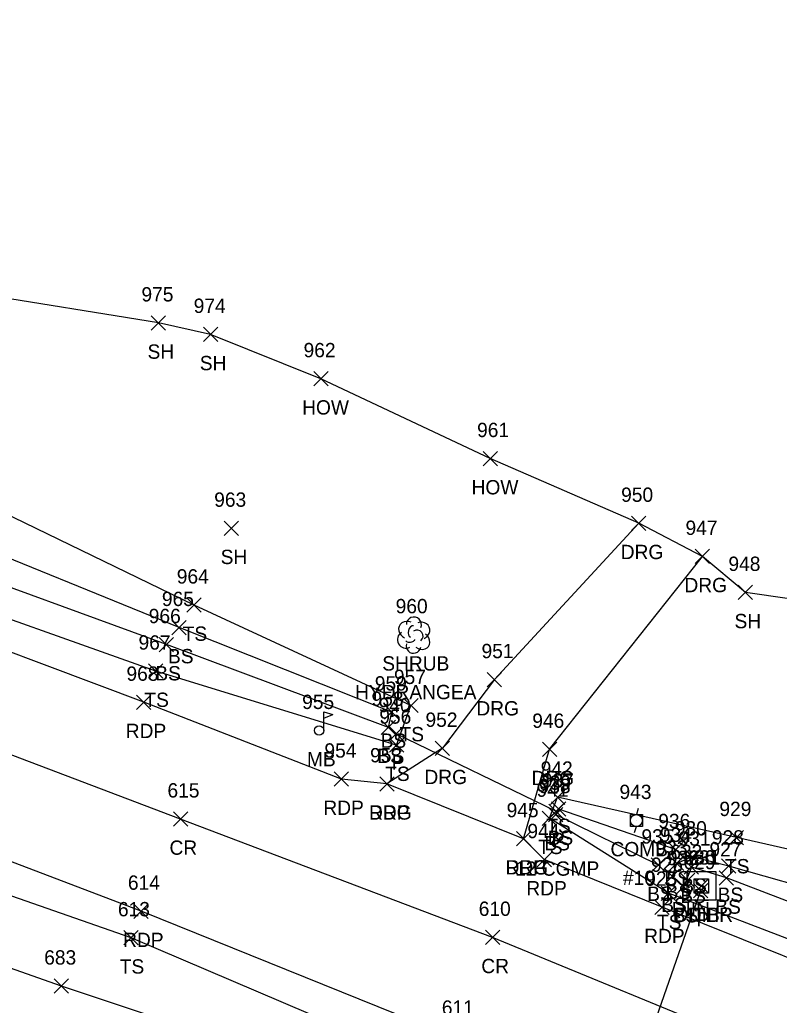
# Model space of a CAD drawing. Extents: x 1599569 to 1610055, y 642560 to 647860.
# Drawn here: x 1602781.6 to 1602887.6, y 647435 to 647572.7 of the extents above; entities that cross this region are included whole.
import ezdxf

# ---------------------------------------------------------------- set-up
doc = ezdxf.new("R2010")
doc.units = 0
for name, color, linetype in [('D_A', 7, 'Continuous'), ('D_C', 7, 'Continuous'), ('D_I', 7, 'Continuous'), ('D_TIC', 7, 'Continuous'), ('DCP', 7, 'Continuous'), ('DS', 7, 'Continuous'), ('L_A', 7, 'Continuous'), ('L_C', 7, 'Continuous'), ('L_I', 7, 'Continuous'), ('L_TIC', 7, 'Continuous'), ('LBC', 7, 'Continuous'), ('LELB', 7, 'Continuous'), ('LMB', 7, 'Continuous'), ('LSH', 7, 'Continuous'), ('LSOGP', 7, 'Continuous'), ('P_A', 7, 'Continuous'), ('P_I', 7, 'Continuous'), ('P_TIC', 7, 'Continuous'), ('PET', 7, 'Continuous'), ('PRC', 7, 'Continuous'), ('R_A', 7, 'Continuous'), ('R_I', 7, 'Continuous'), ('R_TIC', 7, 'Continuous'), ('RDG', 7, 'Continuous'), ('U_A', 7, 'Continuous'), ('U_C', 7, 'Continuous'), ('U_I', 7, 'Continuous'), ('UP', 7, 'Continuous')]:
    doc.layers.add(name, color=color, linetype=linetype)

msp = doc.modelspace()

# ---------------------------------------------------------------- linework, layer by layer
at = {"layer": 'D_TIC'}
for points in [[(1602833.13, 647471.97), (1602835.13, 647473.97)], [(1602835.13, 647471.97), (1602833.13, 647473.97)], [(1602855.42, 647461.14), (1602857.42, 647463.14)], [(1602857.42, 647461.14), (1602855.42, 647463.14)], [(1602873.78, 647451.48), (1602875.78, 647453.48)], [(1602875.78, 647451.48), (1602873.78, 647453.48)], [(1602875.7, 647450.69), (1602877.7, 647452.69)], [(1602877.7, 647450.69), (1602875.7, 647452.69)], [(1602875.62, 647450.06), (1602877.62, 647452.06)], [(1602877.62, 647450.06), (1602875.62, 647452.06)]]:
    msp.add_lwpolyline(points, dxfattribs=at)
at = {"layer": 'DCP'}
for points in [[(1602856.42, 647462.14), (1602834.13, 647472.97)], [(1602857.51, 647396.27), (1602876.62, 647451.06)]]:
    msp.add_lwpolyline(points, dxfattribs=at)
at = {"layer": 'DS'}
for p, q in [((1602874.71, 647453.71), (1602878.71, 647453.71)), ((1602874.71, 647449.71), (1602874.72, 647453.71)), ((1602875.71, 647452.71), (1602877.71, 647452.71)), ((1602875.71, 647450.71), (1602875.71, 647452.71)), ((1602877.71, 647452.71), (1602877.71, 647450.71)), ((1602878.71, 647453.71), (1602878.71, 647449.71)), ((1602876.71, 647451.72), (1602876.71, 647451.72)), ((1602877.71, 647450.71), (1602875.71, 647450.71)), ((1602878.71, 647449.71), (1602874.71, 647449.71)), ((1602877.21, 647449.71), (1602877.71, 647449.71))]:
    msp.add_line(p, q, dxfattribs=at)
at = {"layer": 'L_TIC'}
for points in [[(1602799.94, 647529.33), (1602801.94, 647531.33)], [(1602801.94, 647529.33), (1602799.94, 647531.33)], [(1602807.23, 647527.73), (1602809.23, 647529.73)], [(1602809.23, 647527.73), (1602807.23, 647529.73)], [(1602822.61, 647521.54), (1602824.61, 647523.54)], [(1602824.61, 647521.54), (1602822.61, 647523.54)], [(1602846.25, 647510.39), (1602848.25, 647512.39)], [(1602848.25, 647510.39), (1602846.25, 647512.39)], [(1602810.14, 647500.66), (1602812.14, 647502.66)], [(1602812.14, 647500.66), (1602810.14, 647502.66)], [(1602881.84, 647491.7), (1602883.84, 647493.7)], [(1602883.84, 647491.7), (1602881.84, 647493.7)], [(1602804.92, 647489.94), (1602806.92, 647491.94)], [(1602806.92, 647489.94), (1602804.92, 647491.94)], [(1602802.84, 647486.8), (1602804.84, 647488.8)], [(1602804.84, 647486.8), (1602802.84, 647488.8)], [(1602801.07, 647484.41), (1602803.07, 647486.41)], [(1602803.07, 647484.41), (1602801.07, 647486.41)], [(1602799.58, 647480.71), (1602801.58, 647482.71)], [(1602801.58, 647480.71), (1602799.58, 647482.71)], [(1602835.18, 647475.91), (1602837.18, 647477.91)], [(1602837.18, 647475.91), (1602835.18, 647477.91)], [(1602832.51, 647475), (1602834.51, 647477)], [(1602834.51, 647475), (1602832.51, 647477)], [(1602832.04, 647472.86), (1602834.04, 647474.86)], [(1602834.04, 647472.86), (1602832.04, 647474.86)], [(1602832.04, 647472.86), (1602834.04, 647474.86)], [(1602834.04, 647472.86), (1602832.04, 647474.86)], [(1602833.18, 647470.37), (1602835.18, 647472.37)], [(1602835.18, 647470.37), (1602833.18, 647472.37)], [(1602833.18, 647470.37), (1602835.18, 647472.37)], [(1602835.18, 647470.37), (1602833.18, 647472.37)], [(1602855.65, 647463.1), (1602857.65, 647465.1)], [(1602857.65, 647463.1), (1602855.65, 647465.1)], [(1602855.65, 647463.1), (1602857.65, 647465.1)], [(1602857.65, 647463.1), (1602855.65, 647465.1)], [(1602855.36, 647460.68), (1602857.36, 647462.68)], [(1602857.36, 647460.68), (1602855.36, 647462.68)], [(1602855.36, 647460.68), (1602857.36, 647462.68)], [(1602857.36, 647460.68), (1602855.36, 647462.68)], [(1602855.81, 647461.45), (1602857.81, 647463.45)], [(1602857.81, 647461.45), (1602855.81, 647463.45)], [(1602854.51, 647460.16), (1602856.51, 647462.16)], [(1602856.51, 647460.16), (1602854.51, 647462.16)], [(1602880.59, 647457.47), (1602882.59, 647459.47)], [(1602882.59, 647457.47), (1602880.59, 647459.47)], [(1602872.11, 647455.78), (1602874.11, 647457.78)], [(1602874.11, 647455.78), (1602872.11, 647457.78)], [(1602869.7, 647453.63), (1602871.7, 647455.63)], [(1602871.7, 647453.63), (1602869.7, 647455.63)], [(1602869.7, 647453.63), (1602871.7, 647455.63)], [(1602871.7, 647453.63), (1602869.7, 647455.63)], [(1602872.27, 647453.86), (1602874.27, 647455.86)], [(1602874.27, 647453.86), (1602872.27, 647455.86)], [(1602872.27, 647453.86), (1602874.27, 647455.86)], [(1602874.27, 647453.86), (1602872.27, 647455.86)], [(1602874.44, 647454.76), (1602876.44, 647456.76)], [(1602876.44, 647454.76), (1602874.44, 647456.76)], [(1602879.53, 647453.49), (1602881.53, 647455.49)], [(1602881.53, 647453.49), (1602879.53, 647455.49)], [(1602871.66, 647452.06), (1602873.66, 647454.06)], [(1602873.66, 647452.06), (1602871.66, 647454.06)], [(1602874.32, 647453.34), (1602876.32, 647455.34)], [(1602876.32, 647453.34), (1602874.32, 647455.34)], [(1602879.19, 647451.83), (1602881.19, 647453.83)], [(1602881.19, 647451.83), (1602879.19, 647453.83)], [(1602871.1, 647449.68), (1602873.1, 647451.68)], [(1602873.1, 647449.68), (1602871.1, 647451.68)], [(1602873.25, 647450.62), (1602875.25, 647452.62)], [(1602875.25, 647450.62), (1602873.25, 647452.62)], [(1602796.14, 647443.47), (1602798.14, 647445.47)], [(1602798.14, 647443.47), (1602796.14, 647445.47)], [(1602786.42, 647436.73), (1602788.42, 647438.73)], [(1602788.42, 647436.73), (1602786.42, 647438.73)]]:
    msp.add_lwpolyline(points, dxfattribs=at)
at = {"layer": 'LBC'}
msp.add_lwpolyline([(1602847.25, 647511.39), (1602823.61, 647522.54)], dxfattribs=at)
at = {"layer": 'LELB'}
for points in [[(1602833.04, 647473.86), (1602802.07, 647485.41), (1602768.67, 647497.63), (1602737.77, 647507.38), (1602714.1, 647514.6), (1602693.54, 647524.87), (1602693.84, 647532.12)], [(1602834.18, 647471.37), (1602800.58, 647481.71), (1602766.83, 647493.71), (1602735.94, 647503.84), (1602713.49, 647512.26), (1602692.59, 647522.64), (1602679.82, 647526.83)], [(1602834.18, 647471.37), (1602836.18, 647476.91), (1602805.92, 647490.94), (1602772.81, 647507), (1602747.82, 647515.86)], [(1602833.04, 647473.86), (1602833.51, 647476), (1602803.84, 647487.8), (1602770.45, 647501.41), (1602739.01, 647512.67)], [(1602920.15, 647395.93), (1602878.36, 647413), (1602839.66, 647426.29), (1602797.14, 647444.47), (1602757.03, 647458.46), (1602729.83, 647462.67), (1602705.16, 647473.23), (1602676.17, 647483.37), (1602645.06, 647491.74), (1602608.39, 647499.39), (1602581.9, 647503.71), (1602538.18, 647509.07), (1602515.71, 647510.39), (1602496.95, 647511.81), (1602468.81, 647510.52), (1602437.53, 647504.14), (1602407.66, 647504.45), (1602378.45, 647504.43), (1602350.14, 647499.82), (1602309.52, 647489.18), (1602272.83, 647479.89), (1602236.83, 647468.86)], [(1602844.82, 647413.51), (1602810.8, 647429.9), (1602787.42, 647437.73), (1602740.96, 647454.08), (1602700.04, 647463.04), (1602670.27, 647463.75), (1602639.01, 647474.07), (1602621.95, 647482.89), (1602620.57, 647490.49), (1602611.15, 647487.69), (1602600.84, 647483.48), (1602570.08, 647479.67), (1602551.04, 647482.68)], [(1603024.48, 647432.95), (1603024.71, 647411.16), (1603022.25, 647401.19), (1603020.95, 647395.76), (1603017.49, 647392.33), (1602977.99, 647408.75), (1602939, 647424.29), (1602906.12, 647437.67), (1602872.1, 647450.68), (1602855.51, 647461.16), (1602856.65, 647464.1)], [(1603020.03, 647406.1), (1602986.07, 647424.37), (1602946.6, 647442.8), (1602913.72, 647451.19), (1602881.59, 647458.47), (1602856.65, 647464.1)], [(1602870.7, 647454.63), (1602873.11, 647456.78), (1602856.81, 647462.45), (1602856.36, 647461.68)], [(1602870.7, 647454.63), (1602856.36, 647461.68)], [(1603018.88, 647397.59), (1603018.7, 647403.49), (1602982.82, 647417.97), (1602942.23, 647433.49), (1602910.75, 647445.93), (1602880.53, 647454.49), (1602875.44, 647455.76), (1602873.27, 647454.86)], [(1603018.88, 647397.59), (1602980.19, 647413.24), (1602940.49, 647427.7), (1602908.49, 647441.99), (1602880.19, 647452.83), (1602875.32, 647454.34), (1602874.25, 647451.62), (1602872.66, 647453.06), (1602873.27, 647454.86)]]:
    msp.add_lwpolyline(points, dxfattribs=at)
at = {"layer": 'LMB'}
for p, q in [((1602824.01, 647476.02), (1602825.3, 647475.64)), ((1602824.02, 647473.43), (1602824.01, 647476.02)), ((1602824.01, 647475.12), (1602825.3, 647475.63)), ((1602823.36, 647473.42), (1602823.36, 647473.42))]:
    msp.add_line(p, q, dxfattribs=at)
msp.add_circle((1602823.36, 647473.42), 0.656, dxfattribs=at)
at = {"layer": 'LSH'}
msp.add_line((1602836.55, 647486.79), (1602836.55, 647486.79), dxfattribs=at)
msp.add_line((1602836.55, 647486.79), (1602836.55, 647486.79), dxfattribs=at)
msp.add_arc((1602836.59, 647488.22), 1.05, 335.5272, 180.9563, dxfattribs=at)
for centre, major_axis, ratio, start_param, end_param in [((1602835.75, 647487.45), (1.21, -0.51), 0.895232, 1.570796, 4.712389), ((1602837.59, 647487.37), (-1.14, -0.48), 0.949671, 1.570796, 4.712389), ((1602835.46, 647486.08), (0.58, -1.04), 0.959034, 3.141593, 6.283185), ((1602836.34, 647487.25), (-0.208, -0.792), 0.645439, 3.141593, 6.283185), ((1602837.05, 647486.62), (-0.5, 0.667), 0.989748, 3.141593, 6.283185), ((1602836.09, 647486.04), (-0.625, -0.083), 0.423636, 0, 3.141593), ((1602837.55, 647485.95), (-1.09, 0.79), 0.841452, 1.570796, 4.712389), ((1602836.55, 647485.29), (0.26, 1.06), 0.942809, 1.570796, 4.712389)]:
    msp.add_ellipse(centre, major_axis=major_axis, ratio=ratio, start_param=start_param, end_param=end_param, dxfattribs=at)
at = {"layer": 'LSOGP'}
msp.add_lwpolyline([(1602895.48, 647490.88), (1602882.84, 647492.7), (1602876.85, 647497.73), (1602867.96, 647502.35), (1602847.25, 647511.39), (1602823.62, 647522.54), (1602808.23, 647528.73), (1602800.94, 647530.33), (1602775.58, 647534.44), (1602752.66, 647541.91), (1602749.58, 647545.47), (1602732.53, 647552.91), (1602721.69, 647559.94), (1602714.59, 647563.56), (1602695.08, 647572.68), (1602683.13, 647572.17), (1602662.81, 647569.57), (1602657.01, 647571.28), (1602651.21, 647570.55), (1602637.16, 647571.21)], dxfattribs=at)
at = {"layer": 'P_TIC'}
for points in [[(1602797.9, 647476.36), (1602799.9, 647478.36)], [(1602799.9, 647476.36), (1602797.9, 647478.36)], [(1602825.47, 647465.63), (1602827.47, 647467.63)], [(1602827.47, 647465.63), (1602825.47, 647467.63)], [(1602831.84, 647464.97), (1602833.84, 647466.97)], [(1602833.84, 647464.97), (1602831.84, 647466.97)], [(1602803.05, 647460.06), (1602805.05, 647462.06)], [(1602805.05, 647460.06), (1602803.05, 647462.06)], [(1602850.89, 647457.31), (1602852.89, 647459.31)], [(1602852.89, 647457.31), (1602850.89, 647459.31)], [(1602853.79, 647454.39), (1602855.79, 647456.39)], [(1602855.79, 647454.39), (1602853.79, 647456.39)], [(1602797.53, 647447.18), (1602799.53, 647449.18)], [(1602799.53, 647447.18), (1602797.53, 647449.18)], [(1602870.23, 647447.73), (1602872.23, 647449.73)], [(1602872.23, 647447.73), (1602870.23, 647449.73)], [(1602846.57, 647443.53), (1602848.57, 647445.53)], [(1602848.57, 647443.53), (1602846.57, 647445.53)]]:
    msp.add_lwpolyline(points, dxfattribs=at)
at = {"layer": 'PET'}
for points in [[(1602905.04, 647435.16), (1602871.23, 647448.73), (1602854.79, 647455.39), (1602851.89, 647458.31), (1602832.84, 647465.97), (1602826.47, 647466.63), (1602798.9, 647477.36), (1602764.94, 647490.12), (1602734.4, 647501.05), (1602712.01, 647507.82), (1602692.31, 647514.03), (1602689.68, 647516.42), (1602659.67, 647523.94), (1602639.42, 647528.36)], [(1602921.43, 647398.55), (1602879.84, 647415.39), (1602841.76, 647430.73), (1602798.53, 647448.18), (1602759.07, 647463.24), (1602733.65, 647472.41), (1602708.76, 647480.61), (1602673.93, 647491.11), (1602636.13, 647499.95), (1602599.54, 647506.52), (1602572.66, 647510.09), (1602538.1, 647513.57), (1602515.34, 647514.89), (1602496.48, 647515.72), (1602467.73, 647515.18), (1602434.16, 647513.35), (1602407.64, 647511.45), (1602378.14, 647507.95), (1602349.73, 647503.67), (1602307.56, 647494.3), (1602272.4, 647484.22), (1602235.37, 647472.94)]]:
    msp.add_lwpolyline(points, dxfattribs=at)
at = {"layer": 'PRC'}
msp.add_lwpolyline([(1602927.12, 647412.15), (1602885.11, 647429.06), (1602847.57, 647444.53), (1602804.05, 647461.06), (1602764.54, 647476.04), (1602737.72, 647485.6), (1602711.98, 647494.07), (1602678.09, 647504.18), (1602638.82, 647513.36), (1602602.08, 647520.13), (1602573.57, 647523.94), (1602538.53, 647527.38), (1602522.02, 647528.41), (1602495.43, 647529.4), (1602476.58, 647529.51), (1602450.94, 647528.8), (1602428.92, 647527.79), (1602401.34, 647525.43), (1602374.1, 647521.93), (1602345.43, 647516.91), (1602315.11, 647510.44), (1602285.69, 647502.77), (1602253.57, 647492.91)], dxfattribs=at)
at = {"layer": 'R_TIC'}
for points in [[(1602866.96, 647501.35), (1602868.96, 647503.35)], [(1602868.96, 647501.35), (1602866.96, 647503.35)], [(1602875.85, 647496.73), (1602877.85, 647498.73)], [(1602877.85, 647496.73), (1602875.85, 647498.73)], [(1602846.82, 647479.52), (1602848.82, 647481.52)], [(1602848.82, 647479.52), (1602846.82, 647481.52)], [(1602839.57, 647469.93), (1602841.57, 647471.93)], [(1602841.57, 647469.93), (1602839.57, 647471.93)], [(1602854.53, 647469.79), (1602856.53, 647471.79)], [(1602856.53, 647469.79), (1602854.53, 647471.79)], [(1602831.84, 647464.97), (1602833.84, 647466.97)], [(1602833.84, 647464.97), (1602831.84, 647466.97)], [(1602850.89, 647457.31), (1602852.89, 647459.31)], [(1602852.89, 647457.31), (1602850.89, 647459.31)]]:
    msp.add_lwpolyline(points, dxfattribs=at)
at = {"layer": 'RDG'}
for points in [[(1602867.96, 647502.35), (1602847.82, 647480.52), (1602840.57, 647470.93), (1602832.84, 647465.97)], [(1602851.89, 647458.31), (1602855.53, 647470.79), (1602876.85, 647497.73)]]:
    msp.add_lwpolyline(points, dxfattribs=at)
at = {"layer": 'UP'}
for p, q in [((1602867.89, 647462.52), (1602867.64, 647461.69)), ((1602866.8, 647460.02), (1602866.8, 647461.69)), ((1602866.8, 647461.69), (1602868.47, 647461.69)), ((1602868.47, 647461.69), (1602868.47, 647460.02)), ((1602868.47, 647460.02), (1602866.8, 647460.02)), ((1602867.39, 647459.19), (1602867.64, 647460.02)), ((1602867.64, 647460.85), (1602867.64, 647460.85))]:
    msp.add_line(p, q, dxfattribs=at)
msp.add_circle((1602867.64, 647460.85), 0.833, dxfattribs=at)

# ---------------------------------------------------------------- texts
at = {"layer": 'D_A'}
for s, p in [('P', (1602833.5, 647467.97)), ('P', (1602855.8, 647457.14)), ('DIIN', (1602872.55, 647447.48)), ('DITHR', (1602872.95, 647446.69)), ('DIB', (1602874.8, 647446.69)), ('P', (1602876, 647446.06))]:
    msp.add_text(s, height=2, dxfattribs=at).set_placement(p)
at = {"layer": 'D_C'}
msp.add_text('12 CGMP', height=2, dxfattribs=at).set_placement((1602850.72, 647453.14))
at = {"layer": 'D_I'}
for s, p in [('940', (1602831.68, 647475.97)), ('939', (1602854.05, 647465.14)), ('632', (1602872.37, 647455.48)), ('630', (1602874.2, 647454.69)), ('629', (1602874.2, 647454.06)), ('631', (1602874.88, 647454.69))]:
    msp.add_text(s, height=2, dxfattribs=at).set_placement(p)
at = {"layer": 'L_A'}
for s, p in [('SH', (1602799.43, 647525.33)), ('SH', (1602806.72, 647523.73)), ('HOW', (1602821, 647517.54)), ('HOW', (1602844.64, 647506.39)), ('SH', (1602809.63, 647496.66)), ('SH', (1602881.33, 647487.7)), ('TS', (1602804.33, 647485.94)), ('BS', (1602802.28, 647482.8)), ('SHRUB', (1602832.18, 647481.79)), ('BS', (1602800.51, 647480.41)), ('TS', (1602798.99, 647476.71)), ('TS', (1602834.59, 647471.91)), ('BS', (1602831.95, 647471)), ('BS', (1602831.48, 647468.86)), ('BS', (1602831.48, 647468.86)), ('MB', (1602821.67, 647468.42)), ('TS', (1602832.59, 647466.37)), ('TS', (1602832.59, 647466.37)), ('TS', (1602855.06, 647459.1)), ('TS', (1602855.06, 647459.1)), ('TS', (1602853.92, 647456.16)), ('BS', (1602854.8, 647456.68)), ('BS', (1602854.8, 647456.68)), ('BS', (1602855.25, 647457.45)), ('TS', (1602880, 647453.47)), ('BS', (1602871.55, 647451.78)), ('BS', (1602873.89, 647450.76)), ('BS', (1602869.14, 647449.63)), ('BS', (1602869.14, 647449.63)), ('BS', (1602871.71, 647449.86)), ('BS', (1602871.71, 647449.86)), ('BS', (1602873.76, 647449.34)), ('BS', (1602878.97, 647449.49)), ('BS', (1602871.1, 647448.06)), ('BS', (1602872.69, 647446.62)), ('BS', (1602878.64, 647447.83)), ('TS', (1602870.51, 647445.68)), ('TS', (1602795.55, 647439.47))]:
    msp.add_text(s, height=2, dxfattribs=at).set_placement(p)
at = {"layer": 'L_C'}
msp.add_text('HYDRANGEA', height=2, dxfattribs=at).set_placement((1602828.38, 647477.79))
at = {"layer": 'L_I'}
for s, p in [('975', (1602798.58, 647533.33)), ('974', (1602805.87, 647531.73)), ('962', (1602821.2, 647525.54)), ('961', (1602845.41, 647514.39)), ('963', (1602808.73, 647504.66)), ('948', (1602880.48, 647495.7)), ('964', (1602803.51, 647493.94)), ('965', (1602801.43, 647490.8)), ('960', (1602834.05, 647489.79)), ('966', (1602799.6, 647488.41)), ('967', (1602798.17, 647484.71)), ('957', (1602833.81, 647479.91)), ('959', (1602831.14, 647479)), ('958', (1602830.68, 647476.86)), ('958', (1602830.68, 647476.86)), ('955', (1602821, 647476.42)), ('956', (1602831.77, 647474.37)), ('956', (1602831.77, 647474.37)), ('942', (1602854.29, 647467.1)), ('942', (1602854.29, 647467.1)), ('938', (1602854, 647464.68)), ('938', (1602854, 647464.68)), ('937', (1602854.45, 647465.45)), ('941', (1602853.71, 647464.16)), ('929', (1602879.22, 647461.47)), ('936', (1602870.69, 647459.78)), ('935', (1602868.34, 647457.63)), ('935', (1602868.34, 647457.63)), ('934', (1602870.91, 647457.86)), ('934', (1602870.91, 647457.86)), ('930', (1602873, 647458.76)), ('931', (1602873.52, 647457.34)), ('928', (1602878.17, 647457.49)), ('933', (1602870.3, 647456.06)), ('927', (1602877.83, 647455.83)), ('926', (1602869.68, 647453.68)), ('932', (1602871.89, 647454.62)), ('613', (1602795.3, 647447.47)), ('683', (1602785.01, 647440.73))]:
    msp.add_text(s, height=2, dxfattribs=at).set_placement(p)
at = {"layer": 'P_A'}
for s, p in [('RDP', (1602796.39, 647472.36)), ('RDP', (1602823.96, 647461.63)), ('RDP', (1602830.33, 647460.97)), ('CR', (1602802.49, 647456.06)), ('RDP', (1602849.38, 647453.31)), ('RDP', (1602852.28, 647450.39)), ('RDP', (1602796.02, 647443.18)), ('RDP', (1602868.72, 647443.73)), ('CR', (1602846, 647439.53))]:
    msp.add_text(s, height=2, dxfattribs=at).set_placement(p)
at = {"layer": 'P_I'}
for s, p in [('968', (1602796.49, 647480.36)), ('954', (1602824.11, 647469.63)), ('953', (1602830.48, 647468.97)), ('615', (1602802.21, 647464.06)), ('945', (1602849.53, 647461.31)), ('944', (1602852.43, 647458.39)), ('614', (1602796.69, 647451.18)), ('925', (1602868.87, 647451.73)), ('610', (1602845.64, 647447.53)), ('611', (1602840.49, 647433.73))]:
    msp.add_text(s, height=2, dxfattribs=at).set_placement(p)
at = {"layer": 'R_A'}
for p in [(1602865.45, 647497.35), (1602874.34, 647492.73), (1602845.31, 647475.52), (1602838.06, 647465.93), (1602853.01, 647465.79), (1602830.33, 647460.97), (1602849.38, 647453.31)]:
    msp.add_text('DRG', height=2, dxfattribs=at).set_placement(p)
at = {"layer": 'R_I'}
for s, p in [('950', (1602865.51, 647505.35)), ('947', (1602874.49, 647500.73)), ('951', (1602846.03, 647483.52)), ('952', (1602838.21, 647473.93)), ('946', (1602853.11, 647473.79)), ('953', (1602830.48, 647468.97)), ('945', (1602849.53, 647461.31))]:
    msp.add_text(s, height=2, dxfattribs=at).set_placement(p)
at = {"layer": 'U_A'}
msp.add_text('COMB', height=2, dxfattribs=at).set_placement((1602864.02, 647455.85))
at = {"layer": 'U_C'}
msp.add_text('#10', height=2, dxfattribs=at).set_placement((1602865.76, 647451.85))
at = {"layer": 'U_I'}
msp.add_text('943', height=2, dxfattribs=at).set_placement((1602865.28, 647463.85))

doc.saveas('drawing.dxf')
